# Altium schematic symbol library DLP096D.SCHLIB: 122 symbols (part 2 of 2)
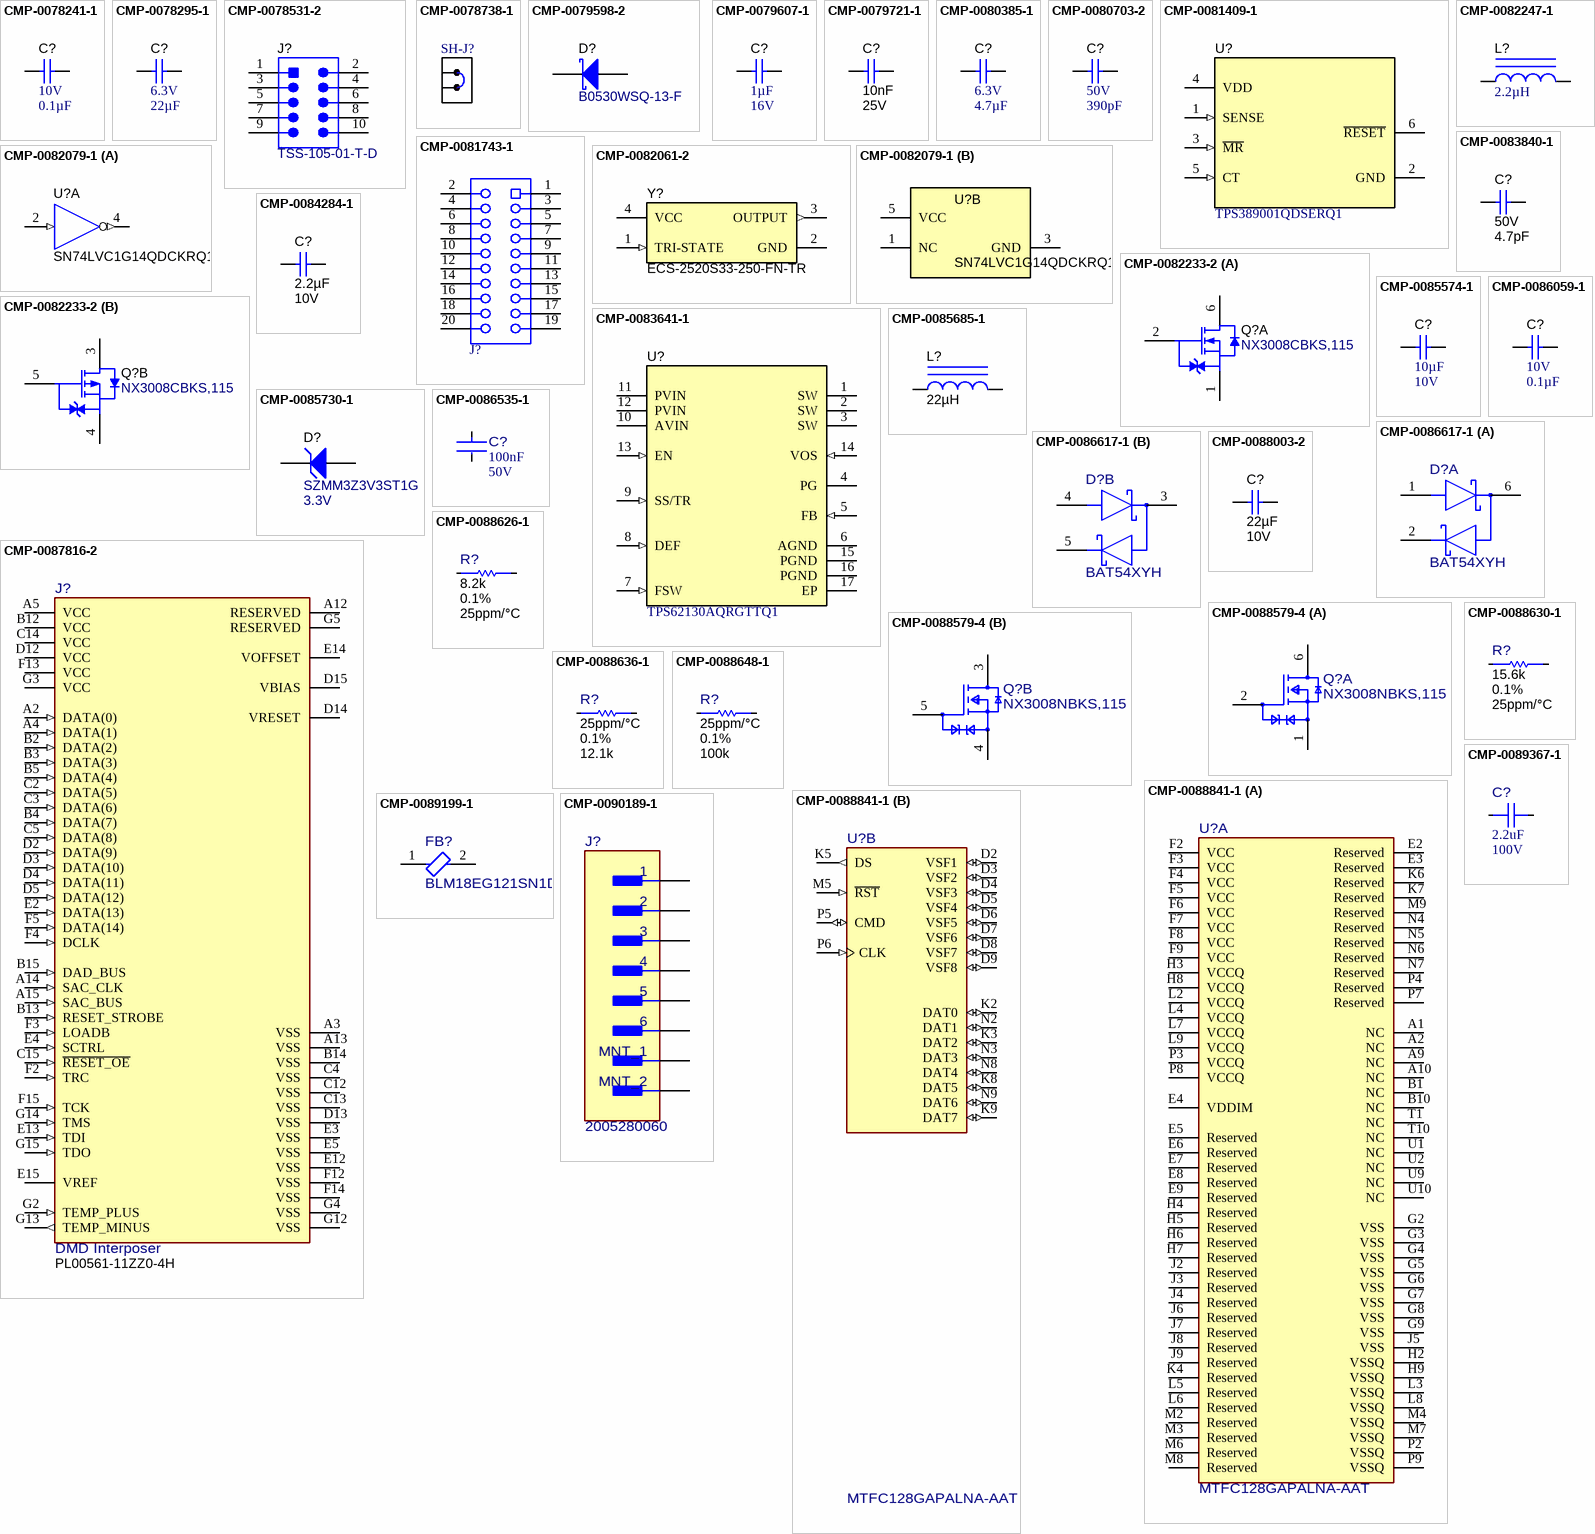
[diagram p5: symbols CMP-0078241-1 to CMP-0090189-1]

## CMP-0082079-1
designator U?, comment SN74LVC1G14QDCKRQ1
Automotive Single Schmitt-Trigger Inverter, DCK0005A (SOT-SC70-5); Alternate Manufacturer: Texas Instruments; SizeAreaWB_mm2: 9.3; SizeZ_mm: 1.1; SizeX_mm: 2.1; SizeY_mm: 2; SizeArea_mm2: 4.2; CompType: IC; AEC Qualified: Y; AEC Category: Q200
footprint DCK0005A_N (SOT353, 5-Leads, Body 2x1.3mm, Pitch 0.65mm, Lead Span 2.1mm, IPC Medium Density)
footprint DCK0005A_M (SOT353, 5-Leads, Body 2x1.3mm, Pitch 0.65mm, Lead Span 2.1mm, IPC Low Density)
footprint DCK0005A_L (SOT353, 5-Leads, Body 2x1.3mm, Pitch 0.65mm, Lead Span 2.1mm, IPC High Density)
part A pins: 2 A (in), 4 Y (out)
part B pins: 1 NC "Ground", 3 GND (power) "Ground Pin", 5 VCC (power) "Power Pin"

## CMP-0082233-2
designator Q?, comment NX3008CBKS,115
MOSFET, 2-CH, N/P-CH, -30 V, -0.2 A, AEC-Q101, SOT-363; Manufacturer: Nexperia; Alternate Manufacturer: None; SizeAreaWB_mm2: 10.24; Value2: 0.55 nC; Rdson45_ohm: 4.1; Value1: 4.1 ohm; SizeX_mm: 2.2; Value: -30V; ChMode: Enhancement; Vgs_V: -8V; SizeArea_mm2: 4.84; AEC Qualified: Y; AEC Category: Q101; ChType: P; QgTyp_nC: 0.55; IdsMax_A: -200mA; SizeZ_mm: 1.1
footprint SOT-363
part A pins: 1 S, 2 G, 6 D
part B pins: 3 D, 4 S, 5 G

## CMP-0082247-1
designator L?, comment ValueDisplayed: 2.2µH  (hidden comment: MLP2012V2R2MT0S1)
Inductor, Shielded, Ferrite, 2.2 µH, 0.7 A, 0.364 ohm, SMD; Manufacturer: TDK; Irms: 0.7A @ 40C rise; SizeAreaWB_mm2: 6.75; DCR_ohm: 0.364; Value: 2.2uH; Imax_A: 700mA; SizeZ_mm: 1.45; SizeX_mm: 2; SizeY_mm: 1.25; Value2: 0.7A; SizeArea_mm2: 2.5; AEC Qualified: N; AEC Category: Q200
footprint 0805_HV (0805 with 30mil clearance between pads)
footprint 0805_HV1 (Custom footprint based on analyzing multiple manufacturer recommendations)
footprint 0805 (0805 from SM-752 data)
footprint 0805M (0805 from SM-752 data)
footprint 0805L (0805 from SM-752 data)
pins: 1, 2

## CMP-0083641-1
designator U?, comment TPS62130AQRGTTQ1
TPS62130A-Q1 3 to 17-V 3-A Automotive Step-Down Converter in 3 × 3 QFN Package, RGT0016C (VQFN-16); Alternate PartNumber: TPS62130AQRGTRQ1; Alternate Manufacturer: Texas Instruments; SizeAreaWB_mm2: 16; SizeZ_mm: 1; SizeX_mm: 3; SizeArea_mm2: 9; CompType: IC; AEC Qualified: Y; AEC Category: Q200
footprint RGT0016C (QFN, 16-Leads, Body 3x3mm, Pitch 0.5mm, Thermal Pad 1.7x1.7mm, TI Recommended)
pins: 1 SW (power) "Switch node, which is connected to the internal MOSFET switches. Connect inductor between SW and output capacitor.", 2 SW (power) "Switch node, which is connected to the internal MOSFET switches. Connect inductor between SW and output capacitor.", 3 SW (power) "Switch node, which is connected to the internal MOSFET switches. Connect inductor between SW and output capacitor.", 4 PG (oc) "Output power good (High = VOUT ready, Low = VOUT below nominal regulation) ; open drain (requires pull-up resistor)", 5 FB (in) "Voltage feedback pin. Connect resistive voltage divider to this pin.", 6 AGND (power) "Analog Ground. Must be connected directly to the Exposed Thermal Pad and common ground plane.", 7 FSW (in) "This pin is used for internal logic and must be connected to GND.", 8 DEF (in) "Output Voltage Scaling (Low = nominal, High = nominal + 5%)(2)", 9 SS/TR (in) "Soft-Start / Tracking Pin. An external capacitor connected to this pin sets the internal voltage reference rise time. It can be used for tracking and sequencing.", 10 AVIN (power) "Supply voltage for control circuitry. Connect to same source as PVIN.", 11 PVIN (power) "Supply voltage for power stage. Connect to same source as AVIN.", 12 PVIN (power) "Supply voltage for power stage. Connect to same source as AVIN.", 13 EN (in) "Enable input (High = enabled, Low = disabled)(2)", 14 VOS (in) "Output voltage sense pin and connection for the control loop circuitry.", 15 PGND (power) "Power Ground. Must be connected directly to the Exposed Thermal Pad and common ground plane.", 16 PGND (power) "Power Ground. Must be connected directly to the Exposed Thermal Pad and common ground plane.", 17 EP (power) "Must be connected to AGND (pin 6), PGND (pin 15,16) and common ground plane(3). Must be soldered to achieve appropriate power dissipation and mechanical reliability."

## CMP-0083840-1
designator C?, comment VDC_V: 50V  ValueDisplayed: 4.7pF  (hidden comment: GCM1555C1H4R7CA16D)
CAP, CERM, 4.7 pF, 50 V,+/- 5.3%, C0G/NP0, AEC-Q200 Grade 1, 0402; Manufacturer: MuRata; SizeAreaWB_mm2: 3; SizeArea_mm2: 0.5; AEC Qualified: Y; AEC Category: Q200; Value: 4.7pF; TaMax_C: 125°C; SizeZ_mm: 0.6; AEC Grade: 1; Polarized: N; TaMin_C: -55°C; U/M: EA; CompType: Capacitor; Cap_Case: 0402
footprint 0402 (0402 from SM-752 data)
footprint 0402M (0402 from SM-752 data)
footprint 0402L (0402 from SM-752 data)
footprint 0402S (Based on C0402S footprint from PADS legacy)
pins: 1, 2

## CMP-0084284-1
designator C?, comment Cap_F: 2.2µF  VDC_V: 10V  (hidden comment: GRM188R71A225KE15J)
CAP, CERM, 2.2 µF, 10 V,+/- 10%, X7R, AEC-Q200 Grade 1, 0603; Manufacturer: MuRata; SizeAreaWB_mm2: 4.68; Polarized: N; AEC Qualified: Y; SizeX_mm: 1.6; SizeZ_mm: 1; SizeY_mm: 0.8; U/M: EA; TaMin_C: -55°C; Value: 2.2uF; Cap_Case: 0603; AEC Category: Q200; TaMax_C: 125°C; CompType: Capacitor; SizeArea_mm2: 1.28
footprint 0603 (0603 from SM-752 data)
footprint 0603M (0603 from SM-752 data)
footprint 0603L (0603 from SM-752 data)
footprint 0603_HV (Ernesto recommended land pattern.  26 mil between pads.)
footprint 0603S
pins: 1, 2

## CMP-0085574-1
designator C?, comment ValueDisplayed: 10µF  VDC_V: 10V  (hidden comment: CC0805ZKY5V6BB106)
CAP, CERM, 10 µF, 10 V,+80/-20%, Y5V, 0805; Manufacturer: Yageo; CompType: Capacitor; AEC Category: Q200; Cap_Case: 0805; SizeY_mm: 1.25; AEC Qualified: N; SizeX_mm: 2; Tolerance_%: 80%; TaMax_C: 85°C; TaMin_C: -30°C; Green_Lifecycle: Active; Green_REACh: Incomplete; Value: 10uF; U/M: EA; SizeAreaWB_mm2: 6.75; SizeZ_mm: 1.45; SizeArea_mm2: 2.5
footprint 0805_HV (0805 with 30mil clearance between pads)
footprint 0805_HV1 (Custom footprint based on analyzing multiple manufacturer recommendations)
footprint 0805 (0805 from SM-752 data)
footprint 0805M (0805 from SM-752 data)
footprint 0805L (0805 from SM-752 data)
pins: 1, 2

## CMP-0085685-1
designator L?, comment ValueDisplayed: 22µH  (hidden comment: SRN5040TA-220M)
Inductor, Semi-Shielded, Ferrite, 22 µH, 1.5 A, 0.1476 ohm, AEC-Q200 Grade 1, SMD; Manufacturer: Bourns; Irms: 1.5A @ 40C rise; AEC Category: Q200; DCR_ohm: 0.1476; AEC Qualified: Y; SizeArea_mm2: 24.5025; SizeY_mm: 4.95; Isat: 1.62A @ 30% inductance drop; SizeZ_mm: 4.1; SizeAreaWB_mm2: 35.4025; AEC Grade: 1; Value2: 1.5A; Value: 22uH
footprint SRN5040TA (Bourns)
pins: 1, 2

## CMP-0085730-1
designator D?, comment SZMM3Z3V3ST1G  value 3.3V
Diode, Zener, 3.3 V, 300 mW, AEC-Q101, SOD-323; Manufacturer: ON Semiconductor; RJA_CperW: 416; AEC Qualified: Y; SizeArea_mm2: 3.645; SizeX_mm: 2.7; SizeY_mm: 1.35; SizeZ_mm: 1; AEC Category: Q101; SizeAreaWB_mm2: 8.695; Power_W: 300mW; Value1: 0.3W
footprint SOD-323 (NXP recommended land pattern)
footprint SOD-123
pins: 1 K, 2 A

## CMP-0086059-1
designator C?, comment VDC_V: 10V  ValueDisplayed: 0.1µF  (hidden comment: GRM033R61A104KE84D)
CAP, CERM, 0.1 µF, 10 V,+/- 10%, X5R, 0201; Manufacturer: MuRata; AEC Category: Q200; Cap_F: 100nF; Value: 0.1uF; SizeY_mm: 0.3; AEC Qualified: N; SizeAreaWB_mm2: 2.08; Cap_Case: 0201; SizeArea_mm2: 0.18; CompType: Capacitor; SizeZ_mm: 0.33; SizeX_mm: 0.6; TaMax_C: 85°C; TaMin_C: -55°C; U/M: EA
footprint 0201_033 (SMD, 2-Leads, Height 0.33mm)
footprint 0201_033M (0201)
footprint 0201_033L (0201)
pins: 1, 2

## CMP-0086535-1
designator C?, comment Cap_F: 100nF  VDC_V: 50V  (hidden comment: GCM188L81H104KA57D)
0.1µF ±10% 50V Ceramic Capacitor X8L 0603 (1608 Metric); Manufacturer: Murata Electronics North America; Symbol Name: SYM-GCM188L81H104KA57D; AEC Qualified: Yes; TempCo: -40+15%; SizeZ_mm: 0.9mm; AEC Grade: Grade 0
footprint FP-GCM188L81H104KA57D_0603-MFG
footprint FP-GCM188L81H104KA57D_0603-IPC_C
footprint FP-GCM188L81H104KA57D_0603-IPC_B
footprint FP-GCM188L81H104KA57D_0603-IPC_A
pins: 1, 2

## CMP-0086617-1
designator D?, comment BAT54XYH
Diode Array 2 Pair Series Connection Schottky 30V 200mA (DC) Surface Mount 6-TSSOP, SC-88, SOT-363; Manufacturer: Nexperia; SizeZ_mm: 1.1mm; TJmax_C: 125°C; Symbol Name: SYM-BAT54XYH; AEC Qualified: Yes
footprint FP-BAT54XYH_SOT363-MFG
footprint FP-BAT54XYH_SOT363-IPC_C
footprint FP-BAT54XYH_SOT363-IPC_B
footprint FP-BAT54XYH_SOT363-IPC_A
part A pins: 1 anode_1, 2 cathode_2, 6 cathode1/anode2
part B pins: 3 anode3/cathode4, 4 anode4, 5 cathode3

## CMP-0087816-2
designator J?, comment DMD Interposer  PartNumber: PL00561-11ZZ0-4H
NTERPOSER, 56 CONTACT, HOLE DATUM; Alternate Manufacturer: Neoconix; Alternate PartNumber: BDX0056DMMSXAU00; Manufacturer: Foxconn Interconnect Technology; Symbol Name: SYM-2516672; DUT-Pitch_mm: 1mm; SizeZ_mm: 1.4mm
footprint FP-2516672_SMD_CONN_LGA-56-MFG
footprint CONN_47346-0001
pins: A2 DATA(0) (in), A3 VSS (power), A4 DATA(1) (in), A5 VCC, A12 RESERVED, A13 VSS (power), A14 SAC_CLK (in), A15 SAC_BUS (in), B2 DATA(2) (in), B3 DATA(3) (in), B4 DATA(7) (in), B5 DATA(4) (in), B12 VCC (power), B13 RESET_STROBE (in), B14 VSS (power), B15 DAD_BUS (in), C2 DATA(5) (in), C3 DATA(6) (in), C4 VSS (power), C5 DATA(8) (in), C12 VSS (power), C13 VSS (power), C14 VCC (power), C15 ~{RESET_OE} (in), D2 DATA(9) (in), D3 DATA(10) (in), D4 DATA(11) (in), D5 DATA(12) (in), D12 VCC (power), D13 VSS (power), D14 VRESET (power), D15 VBIAS, E2 DATA(13) (in), E3 VSS (power), E4 SCTRL (in), E5 VSS (power), E12 VSS (power), E13 TDI (in), E14 VOFFSET (power), E15 VREF (power), F2 TRC (in), F3 LOADB (in), F4 DCLK (in), F5 DATA(14) (in), F12 VSS (power), F13 VCC (power), F14 VSS (power), F15 TCK (in), G2 TEMP_PLUS (in), G3 VCC (power), G4 VSS (power), G5 RESERVED, G12 VSS (power), G13 TEMP_MINUS (out), G14 TMS (in), G15 TDO (in)

## CMP-0088003-2
designator C?, comment ValueDisplayed: 22µF  VDC_V: 10V  (hidden comment: CGA5L1X7S1A226M160AC)
CAP CER 22UF 10V X7S 1206; Manufacturer: TDK; TempCo: 30ppm/°C; AEC Qualified: Yes; Tolerance_%: 20%; SizeZ_mm: 1.9mm; Value: 22µF
footprint 1206_190
footprint 1206_190L (1206_190)
footprint 1206_190M (1206_190)
pins: 1, 2

## CMP-0088579-4
designator Q?, comment NX3008NBKS,115
MOSFET 2N-CH 30V 0.35A 6TSSOP; Manufacturer: Nexperia; AEC Qualified: Yes; ChMode: False; Rthja Max: 390K/W; Turn Off Delay Time: 69ns; Rdson45_ohm: 1; Number Of N Channels: 2; Vgs_V: 8V; Pulse Drain Current: 1.4A; TaMin_C: -55°C; TaMax_C: +150°C; Turn On Delay Time: 15ns; AEC Grade: Grade 0; Transconductance: 0.31S; Threshold Vgs Min: 0.6V; Threshold Vgs Max: 1.1V; Input Capacitace At Vds: 34pF @ 15V; SizeZ_mm: 1.1mm; IdsMax_A: 350mA; QgTyp_nC: 0.52nC @ 4.5V; Power_W: 445mW; Typ Forward Diode Voltage: 0.85V; VdsMax_V: 1.2V
footprint FP-NX3008NBKS,115_TSSOP6-MFG
footprint FP-NX3008NBKS,115_TSSOP6-IPC_C
footprint FP-NX3008NBKS,115_TSSOP6-IPC_B
footprint FP-NX3008NBKS,115_TSSOP6-IPC_A
part A pins: 1 S1, 2 G1, 6 D1
part B pins: 3 D2, 4 S2, 5 G2

## CMP-0088626-1
designator R?, comment Res_ohm: 8.2k  Tolerance_%: 0.1%  TempCo: 25ppm/°C  (hidden comment: ERA-2AEB822X)
Res Thin Film 0402 8.2K Ohm 0.1% 0.063W(1/16W) ±25ppm/C Pad SMD Automotive T/R; Manufacturer: Panasonic Electronic Components; VDC_V: 50V; AEC Grade: Grade 0; SizeZ_mm: 0.4mm; AEC Qualified: Yes; Power_W: 63mW
footprint FP-ERA-2AEB822X_0402-MFG
footprint FP-ERA-2AEB822X_0402-IPC_C
footprint FP-ERA-2AEB822X_0402-IPC_B
footprint FP-ERA-2AEB822X_0402-IPC_A
pins: 1, 2

## CMP-0088630-1
designator R?, comment Res_ohm: 15.6k  Tolerance_%: 0.1%  TempCo: 25ppm/°C  (hidden comment: TNPW040215K6BEED)
Res Thin Film 0402 15.6K Ohm 0.1% 1/10W ±25ppm/°C Molded SMD Paper T/R; Manufacturer: Vishay; Power_W: 100mW; SizeZ_mm: 0.4mm; AEC Qualified: Yes; AEC Grade: Grade 0; VDC_V: 50V
footprint FP-TNPW040215K6BEED_0402-MFG
footprint FP-TNPW040215K6BEED_0402-IPC_C
footprint FP-TNPW040215K6BEED_0402-IPC_B
footprint FP-TNPW040215K6BEED_0402-IPC_A
pins: 1, 2

## CMP-0088636-1
designator R?, comment TempCo: 25ppm/°C  Tolerance_%: 0.1%  Res_ohm: 12.1k  (hidden comment: ERA-2AEB1212X)
RES SMD 12.1KOHM 0.1% 1/16W 0402; Manufacturer: Panasonic Electronic Components; SizeZ_mm: 0.4mm; AEC Qualified: Yes; AEC Grade: Grade 0; Power_W: 63mW; VDC_V: 50V
footprint FP-ERA-2AEB1212X_0402-MFG
footprint FP-ERA-2AEB1212X_0402-IPC_C
footprint FP-ERA-2AEB1212X_0402-IPC_B
footprint FP-ERA-2AEB1212X_0402-IPC_A
pins: 1, 2

## CMP-0088648-1
designator R?, comment TempCo: 25ppm/°C  Tolerance_%: 0.1%  Res_ohm: 100k  (hidden comment: ERA-2AEB104X)
Res Thin Film 0402 100K Ohm 0.1% 1/16W ±25ppm/°C Molded SMD SMD Punched Carrier T/R; Manufacturer: Panasonic; Category 7542B8484461Ae85: Passive Components; VDC_V: 50V; Category Cd01000Bfc2916C6: Single Components; Power_W: 63mW; Category 5A00970A6D5C81C7: Uncategorized; AEC Qualified: Yes; SizeZ_mm: 0.4mm; AEC Grade: Grade 0; Category 5C6A91606D4187Ad: Resistors
footprint FP-ERA-2AEB104X_0402-MFG
footprint FP-ERA-2AEB104X_0402-IPC_C
footprint FP-ERA-2AEB104X_0402-IPC_B
footprint FP-ERA-2AEB104X_0402-IPC_A
pins: 1, 2

## CMP-0088841-1
designator U?, comment MTFC128GAPALNA-AAT
e.MMC Memory, 128GB NOR FLASH memory; Manufacturer: Micron; Frequency_Fixed: 200MHz; TaMax_C: +105°C; Standoff Height: 0.316mm; AEC Grade: Grade 2; TaMin_C: -40°C; AEC Qualified: Yes; Nominal Supply Current: 90-150mA; Interface: Other; Memory Size: 128GBytes; SizeZ_mm: 1.2mm; Max Supply Voltage: 3.6V; Min Supply Voltage: 1.7V; Memory Type: FLASH,NAND
footprint FP-MTFC128GAPALNA-AAT_TBGA100-MFG
footprint FP-MTFC128GAPALNA-AAT_TBGA100-IPC_C
footprint FP-MTFC128GAPALNA-AAT_TBGA100-IPC_B
footprint FP-MTFC128GAPALNA-AAT_TBGA100-IPC_A
part A pins: A1 NC, A2 NC, A9 NC, A10 NC, B1 NC, B10 NC, E2 Reserved, E3 Reserved, E4 VDDIM (power), E5 Reserved, E6 Reserved, E7 Reserved, E8 Reserved, E9 Reserved, F2 VCC (power), F3 VCC (power), F4 VCC (power), F5 VCC (power), F6 VCC (power), F7 VCC (power), F8 VCC (power), F9 VCC (power), G2 VSS (power), G3 VSS (power), G4 VSS (power), G5 VSS (power), G6 VSS (power), G7 VSS (power), G8 VSS (power), G9 VSS (power), H2 VSSQ (power), H3 VCCQ (power), H4 Reserved, H5 Reserved, H6 Reserved, H7 Reserved, H8 VCCQ (power), H9 VSSQ (power), J2 Reserved, J3 Reserved, J4 Reserved, J5 VSS (power), J6 Reserved, J7 Reserved, J8 Reserved, J9 Reserved, K4 Reserved, K6 Reserved, K7 Reserved, L2 VCCQ (power), L3 VSSQ (power), L4 VCCQ (power), L5 Reserved, L6 Reserved, L7 VCCQ (power), L8 VSSQ (power), L9 VCCQ (power), M2 Reserved, M3 Reserved, M4 VSSQ (power), M6 Reserved, M7 VSSQ (power), M8 Reserved, M9 Reserved, N4 Reserved, N5 Reserved, N6 Reserved, N7 Reserved, P2 VSSQ (power), P3 VCCQ (power), P4 Reserved, P7 Reserved, P8 VCCQ (power), P9 VSSQ (power), T1 NC, T10 NC, U1 NC, U2 NC, U9 NC, U10 NC
part B pins: D2 VSF1 (io), D3 VSF2 (io), D4 VSF3 (io), D5 VSF4 (io), D6 VSF5 (io), D7 VSF6 (io), D8 VSF7 (io), D9 VSF8 (io), K2 DAT0 (io), K3 DAT2 (io), K5 DS (out), K8 DAT5 (io), K9 DAT7 (io), M5 ~{RST} (in), N2 DAT1 (io), N3 DAT3 (io), N8 DAT4 (io), N9 DAT6 (io), P5 CMD (io), P6 CLK (in)

## CMP-0089199-1
designator FB?, comment BLM18EG121SN1D
120 Ohms @ 100MHz 1  Ferrite Bead 0603 (1608 Metric) 2A 40mOhm; Manufacturer: Murata; DCR_ohm: 60m; AEC Qualified: No; Tolerance_%: 25%; SizeZ_mm: 0.95mm; Impedance At Frequency: 120Ω @ 100MHz
footprint FP-BLM18EG121SN1D_0603-MFG
footprint FP-BLM18EG121SN1D_0603-IPC_C
footprint FP-BLM18EG121SN1D_0603-IPC_B
footprint FP-BLM18EG121SN1D_0603-IPC_A
pins: 1, 2

## CMP-0089367-1
designator C?, comment ValueDisplayed: 2.2uF  VDC_V: 100V  (hidden comment: GCJ32DL8EL225KA07L)
2.2µF ±10% 100V Ceramic Capacitor X8L 1210 (3225 Metric); Manufacturer: Murata; TempCo: +15/-40%; AEC Qualified: Yes; AEC Grade: Grade 0; SizeZ_mm: 2.3mm
footprint FP-GCJ32DL8EL225KA07L_1210-MFG
footprint FP-GCJ32DL8EL225KA07L_1210-IPC_C
footprint FP-GCJ32DL8EL225KA07L_1210-IPC_B
footprint FP-GCJ32DL8EL225KA07L_1210-IPC_A
pins: 1, 2

## CMP-0090189-1
designator J?, comment 2005280060
Manufacturer: Molex; Conn Gender: Male; Is Female: yes; DUT-Pitch_mm: 1mm; ContactFinish: Gold,Nickel; SizeZ_mm: 4.15mm; Conn Orientation: Right Angle; Voltage_V: 125V; AEC Qualified: No; Current_A: 1A
footprint FP-2005280060_CONN_11MM2_5MM25-MFG
pins: 1, 2, 3, 4, 5, 6, 7 MNT_1, 8 MNT_2

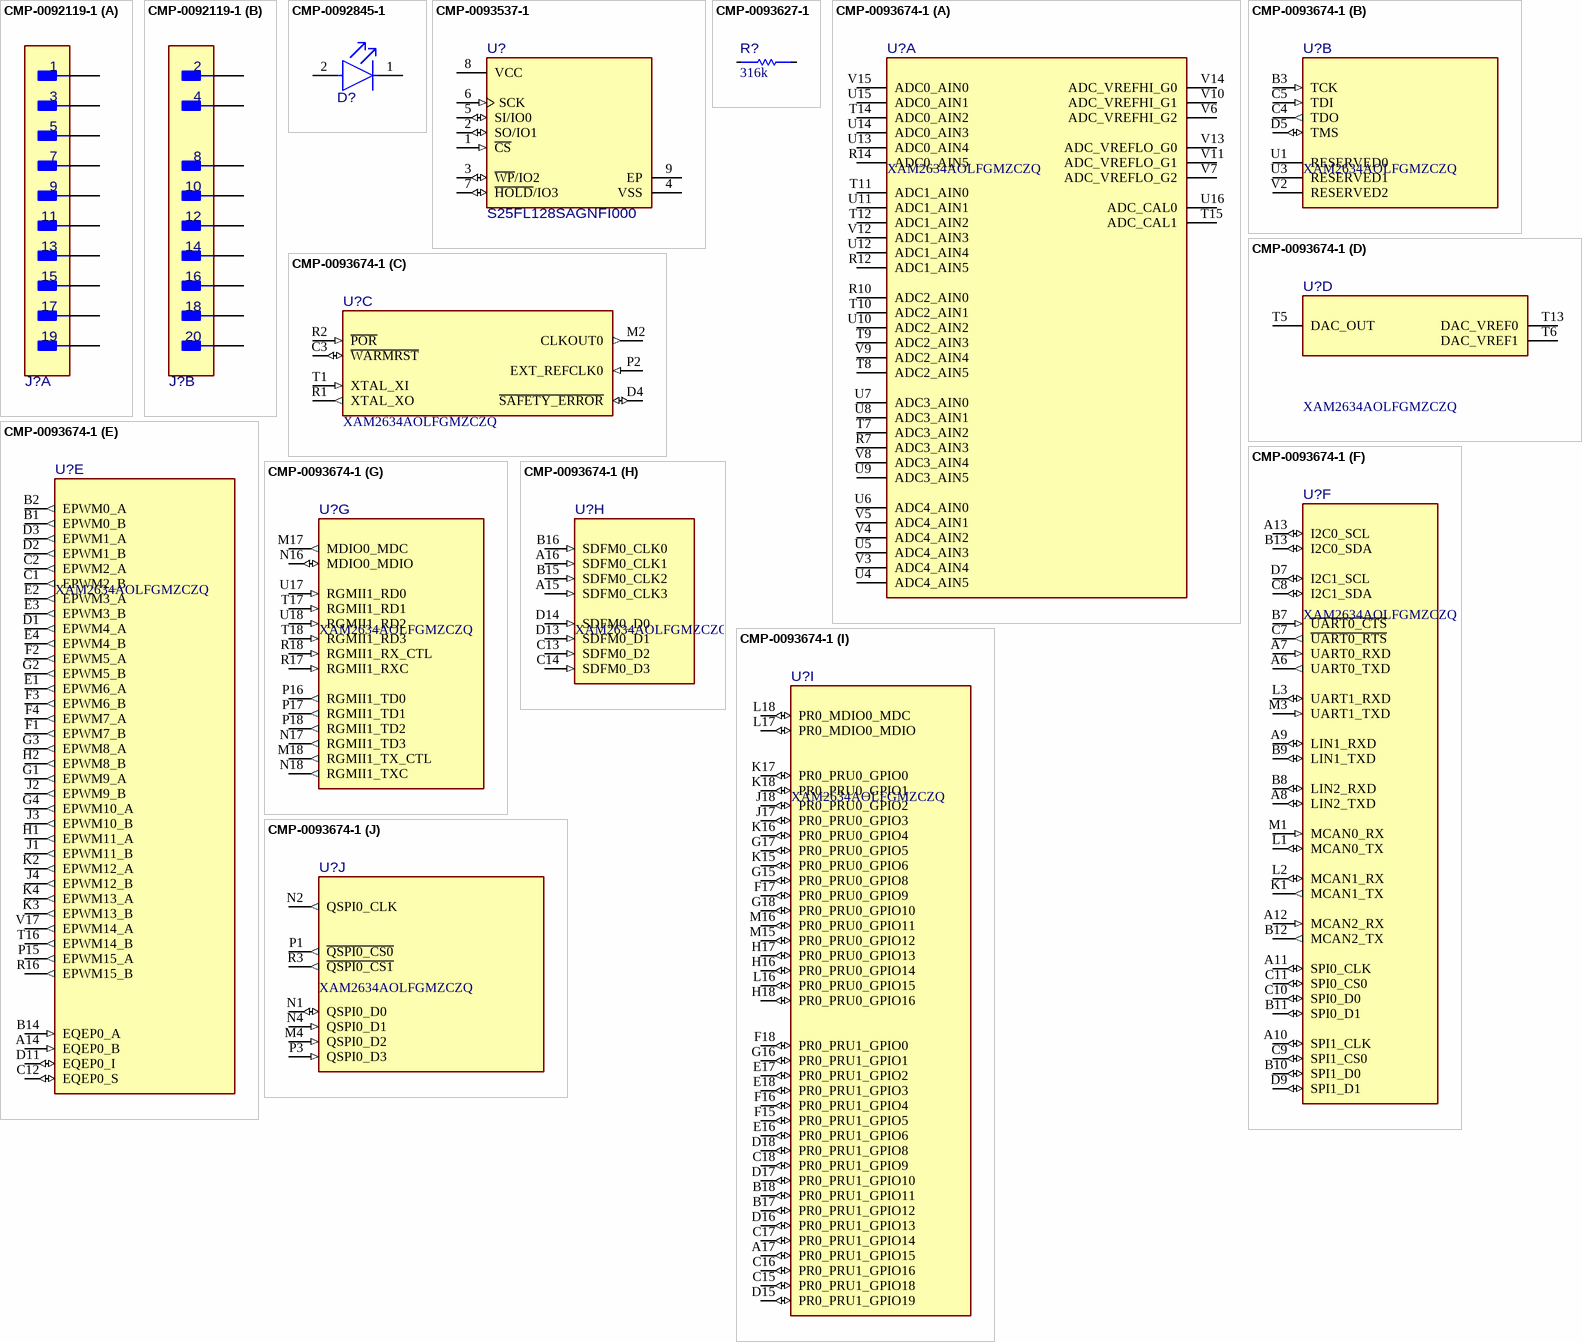
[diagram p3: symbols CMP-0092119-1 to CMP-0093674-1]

## CMP-0092119-1
designator J?, comment FTR-110-03-G-D-06  (value not drawn)
Connector Header Surface Mount 20 position 0.050" (1.27mm); Manufacturer: Samtec; ContactFinish: Gold; Standoff Height: 1mm; Row_Count: 2; AEC Qualified: No; Conn Orientation: Vertical; Current_A: 3.1A; Conn Gender: Male; SizeZ_mm: 7.58mm
footprint FP-FTR-110-03-G-D-06_HDR19-MFG
part A pins: 1, 3, 5, 7, 9, 11, 13, 15, 17, 19
part B pins: 2, 4, 8, 10, 12, 14, 16, 18, 20

## CMP-0092845-1
designator D?, comment LSL29K-G1H2-1-Z  (value not drawn)
LED Uni-Color Red 643nm 2-Pin Chip 0603(1608Metric) T/R; Manufacturer: OSRAM Opto Semiconductors; AEC Grade: Grade 2; LuminousFlux_PhiV: 8.1/16.1lm; Vf_V: 1.8V; Forward Current: 2mA; Led Orientation: Top View; SizeZ_mm: 0.67mm; AEC Qualified: Yes; Luminous Intensity: 1.8-2.24/3.55-4.5mcd; Vr_V: 12V; Angle: 160°; LambdaD: 630nm; Tjmax_C: 110°C
footprint FP-LSL29K-G1H2-1-Z_0603-0
pins: 1 CATHODE, 2 ANODE

## CMP-0093537-1
designator U?, comment S25FL128SAGNFI000
FLASH - NOR Memory IC 128Mb (16M x 8) SPI - Quad I/O 133 MHz 8-WSON (6x8); Manufacturer: Cypress Semiconductor; Nominal Supply Current: 16-100mA; AEC Qualified: No; Max Supply Voltage: 3.6V; Access Time: 8ns; TaMin_C: -40°C; SizeZ_mm: 0.8mm; TaMax_C: +85°C; Standoff Height: 0mm; Memory Size: 128Mbits; Min Supply Voltage: 1.65V; Frequency_Fixed: 133MHz
footprint FP-S25FL128SAGNFI000_WSON8-MFG
footprint FP-S25FL128SAGNFI000_WSON8-IPC_C
footprint FP-S25FL128SAGNFI000_WSON8-IPC_B
footprint FP-S25FL128SAGNFI000_WSON8-IPC_A
pins: 1 ~{CS} (in), 2 SO/IO1 (io), 3 ~{WP}/IO2 (io), 4 VSS (power), 5 SI/IO0 (io), 6 SCK (in), 7 ~{HOLD}/IO3 (io), 8 VCC (power), 9 EP (power)

## CMP-0093627-1
designator R?, comment value 316k  (hidden comment: CR0603-FX-3163ELF)
Thick Film Chip Resistors 0603 316kΩ 0.1W 1% 100ppm/°C; Manufacturer: Bourns; AEC Qualified: No; SizeZ_mm: 0.55mm; Power_W: 100mW; VDC_V: 75V
footprint FP-CR0603-FX-3163ELF_0603-MFG
footprint FP-CR0603-FX-3163ELF_0603-IPC_C
footprint FP-CR0603-FX-3163ELF_0603-IPC_B
footprint FP-CR0603-FX-3163ELF_0603-IPC_A
pins: 1, 2

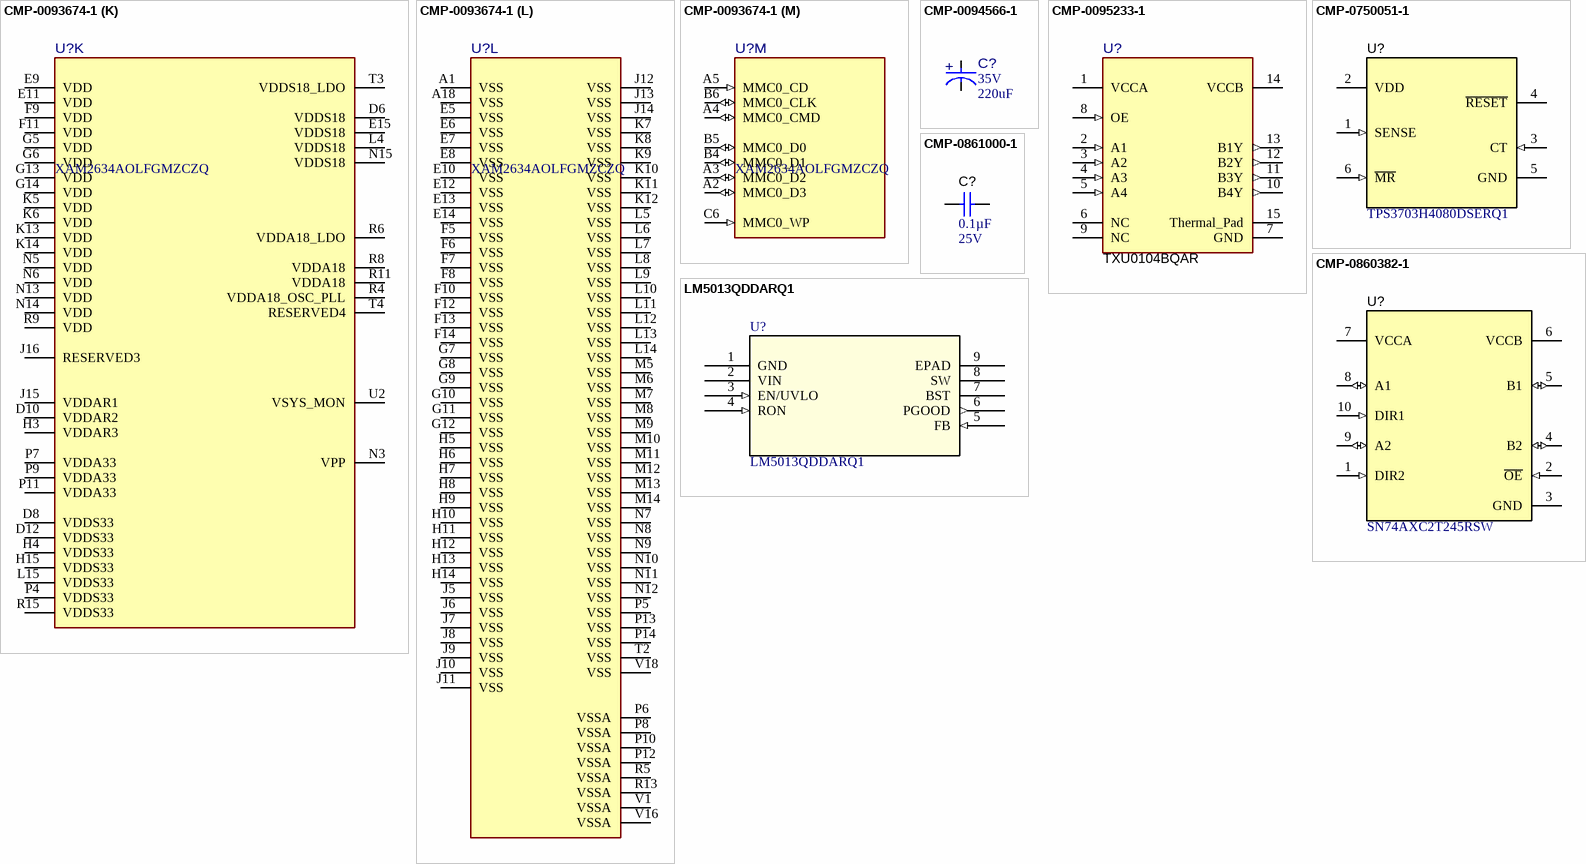
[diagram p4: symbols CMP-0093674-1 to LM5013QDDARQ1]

## CMP-0093674-1
designator U?, comment XAM2634AOLFGMZCZQ
Sitara™ Microcontrollers; Manufacturer: Texas Instruments; Min Supply Voltage: 1.14V; Number Of Adc Channels: 30; AEC Qualified: No; TJmax_C: +105°C; Memory Type: SRAM; Standoff Height: 0.35mm; Core Architecture: ARM Cortex-R5F; Number Of I2C Channels: 4; Number Of Pwm Channels: 24; Number Of Spi Channels: 5; Frequency_Fixed: 400MHz; Nominal Supply Current: 200-2500mA; Ram Size: 2MBytes; Number Of Ethernet Channels: 1; Interface: I2C,SPI,UART,CAN,LIN,Ethernet,Other; Data Bus Width: 64bits; SizeZ_mm: 1.4mm; Number Of Uart Channels: 6; Number Of I/Os: 140; Max Supply Voltage: 3.465V
footprint ZCZ0324A-MFG
footprint ZCZ0324A-IPC_C
footprint ZCZ0324A-IPC_B
footprint ZCZ0324A-IPC_A
part A pins: R7 ADC3_AIN3, R10 ADC2_AIN0, R12 ADC1_AIN5, R14 ADC0_AIN5, T7 ADC3_AIN2, T8 ADC2_AIN5, T9 ADC2_AIN3, T10 ADC2_AIN1, T11 ADC1_AIN0, T12 ADC1_AIN2, T14 ADC0_AIN2, T15 ADC_CAL1, U4 ADC4_AIN5, U5 ADC4_AIN3, U6 ADC4_AIN0, U7 ADC3_AIN0, U8 ADC3_AIN1, U9 ADC3_AIN5, U10 ADC2_AIN2, U11 ADC1_AIN1, U12 ADC1_AIN4, U13 ADC0_AIN4, U14 ADC0_AIN3, U15 ADC0_AIN1, U16 ADC_CAL0, V3 ADC4_AIN4, V4 ADC4_AIN2, V5 ADC4_AIN1, V6 ADC_VREFHI_G2, V7 ADC_VREFLO_G2, V8 ADC3_AIN4, V9 ADC2_AIN4, V10 ADC_VREFHI_G1, V11 ADC_VREFLO_G1, V12 ADC1_AIN3, V13 ADC_VREFLO_G0, V14 ADC_VREFHI_G0, V15 ADC0_AIN0
part B pins: B3 TCK (in), C4 TDO (out), C5 TDI (in), D5 TMS (io), U1 RESERVED0, U3 RESERVED1, V2 RESERVED2
part C pins: C3 ~{WARMRST} (io), D4 ~{SAFETY_ERROR} (io), M2 CLKOUT0 (out), P2 EXT_REFCLK0 (in), R1 XTAL_XO (out), R2 ~{POR} (in), T1 XTAL_XI (in)
part D pins: T5 DAC_OUT, T6 DAC_VREF1, T13 DAC_VREF0
part E pins: A14 EQEP0_B (in), B1 EPWM0_B (out), B2 EPWM0_A (out), B14 EQEP0_A (in), C1 EPWM2_B (out), C2 EPWM2_A (out), C12 EQEP0_S (io), D1 EPWM4_A (out), D2 EPWM1_B (out), D3 EPWM1_A (out), D11 EQEP0_I (io), E1 EPWM6_A (out), E2 EPWM3_A (out), E3 EPWM3_B (out), E4 EPWM4_B (out), F1 EPWM7_B (out), F2 EPWM5_A (out), F3 EPWM6_B (out), F4 EPWM7_A (out), G1 EPWM9_A (out), G2 EPWM5_B (out), G3 EPWM8_A (out), G4 EPWM10_A (out), H1 EPWM11_A (out), H2 EPWM8_B (out), J1 EPWM11_B (out), J2 EPWM9_B (out), J3 EPWM10_B (out), J4 EPWM12_B (out), K2 EPWM12_A (out), K3 EPWM13_B (out), K4 EPWM13_A (out), P15 EPWM15_A (out), R16 EPWM15_B (out), T16 EPWM14_B (out), V17 EPWM14_A (out)
part F pins: A6 UART0_TXD (out), A7 UART0_RXD (in), A8 LIN2_TXD (io), A9 LIN1_RXD (io), A10 SPI1_CLK (io), A11 SPI0_CLK (io), A12 MCAN2_RX (in), A13 I2C0_SCL (io), B7 ~{UART0_CTS} (in), B8 LIN2_RXD (io), B9 LIN1_TXD (io), B10 SPI1_D0 (io), B11 SPI0_D1 (io), B12 MCAN2_TX (out), B13 I2C0_SDA (io), C7 ~{UART0_RTS} (out), C8 I2C1_SDA (io), C9 SPI1_CS0 (io), C10 SPI0_D0 (io), C11 SPI0_CS0 (io), D7 I2C1_SCL (io), D9 SPI1_D1 (io), K1 MCAN1_TX (out), L1 MCAN0_TX (io), L2 MCAN1_RX (io), L3 UART1_RXD (io), M1 MCAN0_RX (in), M3 UART1_TXD (in)
part G pins: M17 MDIO0_MDC (out), M18 RGMII1_TX_CTL (out), N16 MDIO0_MDIO (io), N17 RGMII1_TD3 (out), N18 RGMII1_TXC (out), P16 RGMII1_TD0 (out), P17 RGMII1_TD1 (out), P18 RGMII1_TD2 (out), R17 RGMII1_RXC (in), R18 RGMII1_RX_CTL (in), T17 RGMII1_RD1 (in), T18 RGMII1_RD3 (in), U17 RGMII1_RD0 (in), U18 RGMII1_RD2 (in)
part H pins: A15 SDFM0_CLK3 (in), A16 SDFM0_CLK1 (in), B15 SDFM0_CLK2 (in), B16 SDFM0_CLK0 (in), C13 SDFM0_D2 (in), C14 SDFM0_D3 (in), D13 SDFM0_D1 (in), D14 SDFM0_D0 (in)
part I pins: A17 PR0_PRU1_GPIO15 (io), B17 PR0_PRU1_GPIO12 (io), B18 PR0_PRU1_GPIO11 (io), C15 PR0_PRU1_GPIO18 (io), C16 PR0_PRU1_GPIO16 (io), C17 PR0_PRU1_GPIO14 (io), C18 PR0_PRU1_GPIO9 (io), D15 PR0_PRU1_GPIO19 (io), D16 PR0_PRU1_GPIO13 (io), D17 PR0_PRU1_GPIO10 (io), D18 PR0_PRU1_GPIO8 (io), E16 PR0_PRU1_GPIO6 (io), E17 PR0_PRU1_GPIO2 (io), E18 PR0_PRU1_GPIO3 (io), F15 PR0_PRU1_GPIO5 (io), F16 PR0_PRU1_GPIO4 (io), F17 PR0_PRU0_GPIO9 (io), F18 PR0_PRU1_GPIO0 (io), G15 PR0_PRU0_GPIO8 (io), G16 PR0_PRU1_GPIO1 (io), G17 PR0_PRU0_GPIO5 (io), G18 PR0_PRU0_GPIO10 (io), H16 PR0_PRU0_GPIO14 (io), H17 PR0_PRU0_GPIO13 (io), H18 PR0_PRU0_GPIO16 (io), J17 PR0_PRU0_GPIO3 (io), J18 PR0_PRU0_GPIO2 (io), K15 PR0_PRU0_GPIO6 (io), K16 PR0_PRU0_GPIO4 (io), K17 PR0_PRU0_GPIO0 (io), K18 PR0_PRU0_GPIO1 (io), L16 PR0_PRU0_GPIO15 (io), L17 PR0_MDIO0_MDIO (io), L18 PR0_MDIO0_MDC (io), M15 PR0_PRU0_GPIO12 (io), M16 PR0_PRU0_GPIO11 (io)
part J pins: M4 QSPI0_D2 (in), N1 QSPI0_D0 (io), N2 QSPI0_CLK (out), N4 QSPI0_D1 (in), P1 ~{QSPI0_CS0} (out), P3 QSPI0_D3 (in), R3 ~{QSPI0_CS1} (out)
part K pins: D6 VDDS18 (power), D8 VDDS33 (power), D10 VDDAR2 (power), D12 VDDS33 (power), E9 VDD (power), E11 VDD (power), E15 VDDS18 (power), F9 VDD (power), F11 VDD (power), G5 VDD (power), G6 VDD (power), G13 VDD (power), G14 VDD (power), H3 VDDAR3 (power), H4 VDDS33 (power), H15 VDDS33 (power), J15 VDDAR1 (power), J16 RESERVED3, K5 VDD (power), K6 VDD (power), K13 VDD (power), K14 VDD (power), L4 VDDS18 (power), L15 VDDS33 (power), N3 VPP (power), N5 VDD (power), N6 VDD (power), N13 VDD (power), N14 VDD (power), N15 VDDS18 (power), P4 VDDS33 (power), P7 VDDA33 (power), P9 VDDA33 (power), P11 VDDA33 (power), R4 VDDA18_OSC_PLL (power), R6 VDDA18_LDO (power), R8 VDDA18 (power), R9 VDD (power), R11 VDDA18 (power), R15 VDDS33 (power), T3 VDDS18_LDO (power), T4 RESERVED4, U2 VSYS_MON (power)
part L pins: A1 VSS (power), A18 VSS (power), E5 VSS (power), E6 VSS (power), E7 VSS (power), E8 VSS (power), E10 VSS (power), E12 VSS (power), E13 VSS (power), E14 VSS (power), F5 VSS (power), F6 VSS (power), F7 VSS (power), F8 VSS (power), F10 VSS (power), F12 VSS (power), F13 VSS (power), F14 VSS (power), G7 VSS (power), G8 VSS (power), G9 VSS (power), G10 VSS (power), G11 VSS (power), G12 VSS (power), H5 VSS (power), H6 VSS (power), H7 VSS (power), H8 VSS (power), H9 VSS (power), H10 VSS (power), H11 VSS (power), H12 VSS (power), H13 VSS (power), H14 VSS (power), J5 VSS (power), J6 VSS (power), J7 VSS (power), J8 VSS (power), J9 VSS (power), J10 VSS (power), J11 VSS (power), J12 VSS (power), J13 VSS (power), J14 VSS (power), K7 VSS (power), K8 VSS (power), K9 VSS (power), K10 VSS (power), K11 VSS (power), K12 VSS (power), L5 VSS (power), L6 VSS (power), L7 VSS (power), L8 VSS (power), L9 VSS (power), L10 VSS (power), L11 VSS (power), L12 VSS (power), L13 VSS (power), L14 VSS (power), M5 VSS (power), M6 VSS (power), M7 VSS (power), M8 VSS (power), M9 VSS (power), M10 VSS (power), M11 VSS (power), M12 VSS (power), M13 VSS (power), M14 VSS (power), N7 VSS (power), N8 VSS (power), N9 VSS (power), N10 VSS (power), N11 VSS (power), N12 VSS (power), P5 VSS (power), P6 VSSA (power), P8 VSSA (power), P10 VSSA (power), P12 VSSA (power), P13 VSS (power), P14 VSS (power), R5 VSSA (power), R13 VSSA (power), T2 VSS (power), V1 VSSA (power), V16 VSSA (power), V18 VSS (power)
part M pins: A2 MMC0_D3 (io), A3 MMC0_D2 (io), A4 MMC0_CMD (io), A5 MMC0_CD (in), B4 MMC0_D1 (io), B5 MMC0_D0 (io), B6 MMC0_CLK (io), C6 MMC0_WP (in)

## CMP-0094566-1
designator C?, comment VDC_V: 35V  ValueDisplayed: 220uF  (hidden comment: EEE-TP1V221AV)
220 µF 35 V Aluminum Electrolytic Capacitors Radial, Can - SMD 150mOhm @ 100kHz 3000 Hrs @ 125°C; Manufacturer: Panasonic; IRMS_A: 500mA; SizeZ_mm: 10.8mm; Life: 3000Hours; AEC Qualified: Yes; Cap_F: 220µF; Leakage Current: 77uA; Dissipation Factor: 16%; Esr: 0.15; Tolerance_%: 20%; AEC Grade: Grade 1; Value: 220µF
footprint FP-EEE-TP1V221AV_RADIAL-MFG
pins: 1 CATHODE, 2 ANODE

## CMP-0095233-1
designator U?, comment TXU0104BQAR
Four channel unidirectional level shifter 14-WQFN -40 to 125; Manufacturer: Texas Instruments; V B Min: 1.08V; TaMin_C: -40°C; AEC Qualified: No; TaMax_C: +125°C; Propagation Delay: 8ns; Data Rate: 200Mbits/s; Standoff Height: 0mm; TJmax_C: +150°C; SizeZ_mm: 0.8mm; PositionCount: 1; V A Max: 5.5V; Number Of Inputs: 4; Nominal Supply Current: 2.5uA
footprint BQA0014A-MFG
pins: 1 VCCA (power), 2 A1 (in), 3 A2 (in), 4 A3 (in), 5 A4 (in), 6 NC, 7 GND (power), 8 OE (in), 9 NC, 10 B4Y (out), 11 B3Y (out), 12 B2Y (out), 13 B1Y (out), 14 VCCB (power), 15 Thermal_Pad (power)

## CMP-0750051-1
designator U?, comment PartNumber: TPS3703H4080DSERQ1  (hidden comment: TPS3703A4330DSERQ1)
Overvoltage and Undervoltage Reset IC With Time Delay and Manual Reset, DSE0006A (WSON-6); Alternate Manufacturer: Texas Instruments; AEC Category: Q200; SizeY_mm: 1.5; AEC Qualified: Y; SizeAreaWB_mm2: 6.25; SizeZ_mm: 0.8; SizeArea_mm2: 2.25
footprint DSE0006A (TI recommended land pattern)
pins: 1 SENSE (in), 2 VDD (power), 3 CT (in), 4 ~{RESET} (oc), 5 GND (power), 6 ~{MR} (in)

## CMP-0860382-1
designator U?, comment SN74AXC2T245RSW
SN74AXC2T245RSW, RSW0010A (UQFN-10); Alternate Manufacturer: Texas Instruments; SizeZ_mm: 0.55; AEC Qualified: N; SizeArea_mm2: 2.52; CompType: IC; SizeX_mm: 1.4; SizeY_mm: 1.8; AEC Category: Q200; SizeAreaWB_mm2: 6.72
footprint RSW0010A (QFN, 10-Leads, Body 1.8x1.4 mm, Pitch 0.4mm, TI Recommended)
pins: 1 DIR2 (in), 2 ~{OE} (in), 3 GND (power), 4 B2 (io), 5 B1 (io), 6 VCCB (power), 7 VCCA (power), 8 A1 (io), 9 A2 (io), 10 DIR1 (in)

## CMP-0861000-1
designator C?, comment ValueDisplayed: 0.1µF  VDC_V: 25V  (hidden comment: GCM155L81E104KE02D)
CAP, CERM, 0.1 µF, 25 V,+/- 10%, X8L, AEC-Q200 Grade 0, 0402; Manufacturer: MuRata; U/M: EA; Polarized: N; Cap_F: 100nF; SizeZ_mm: 0.6; SizeY_mm: 0.5; Value: 0.1uF; SizeX_mm: 1; Cap_Case: 0402; AEC Qualified: Y; AEC Grade: 0; SizeAreaWB_mm2: 3; CompType: Capacitor; AEC Category: Q200; TaMin_C: -55°C; TaMax_C: 150°C
footprint 0402 (0402 from SM-752 data)
footprint 0402M (0402 from SM-752 data)
footprint 0402L (0402 from SM-752 data)
footprint 0402S (Based on C0402S footprint from PADS legacy)
pins: 1, 2

## LM5013QDDARQ1
designator U?
6-V to 100-V input, 3.5-A non-synchronous buck DC/DC converter with ultra-low quiescent current (IQ); Mfr_Name: Texas Instruments
footprint POWERPAD8_DDA_TEX
pins: 1 GND, 2 VIN (power), 3 EN/UVLO (in), 4 RON (in), 5 FB (in), 6 PGOOD (out), 7 BST (power), 8 SW (power), 9 EPAD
